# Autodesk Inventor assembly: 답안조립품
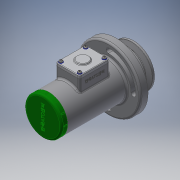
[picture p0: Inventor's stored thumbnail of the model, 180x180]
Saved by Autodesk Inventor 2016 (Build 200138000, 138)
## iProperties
Created: 2017-05
Part Number: 답안조립품
Material: 일반
Document SubType Name: Assembly
Designer: USER
Author: USER
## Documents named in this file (20)
- C:\Users\USER\Desktop\470508V1004\답안조립품.iam
- C:\Users\USER\Desktop\470508V1004\본체.ipt
- C:\Users\USER\Desktop\470508V1004\사이드 커버.ipt
- 사이드 커버.ipt
- C:\Users\USER\Desktop\470508V1004\축.ipt
- C:\Users\USER\Desktop\470508V1004\베어링 15 x 35 x 11.ipt
- C:\Users\USER\Desktop\470508V1004\부시1.ipt
- C:\Users\USER\Desktop\470508V1004\부시2.ipt
- C:\Users\USER\Desktop\470508V1004\멈춤링 35x1.6.ipt
- C:\Users\USER\Desktop\470508V1004\와셔 10x21.ipt
- C:\Users\USER\Desktop\470508V1004\너트 M10.ipt
- C:\Users\USER\Desktop\470508V1004\멈춤링 15 x 1.ipt
- C:\Users\USER\Desktop\470508V1004\오일 실 15 25 7.ipt
- C:\Users\USER\Desktop\470508V1004\탑 커버.ipt
- C:\Users\USER\Desktop\470508V1004\십자볼트 M3 x 10.ipt
- C:\Users\USER\Desktop\470508V1004\와셔 3x6.ipt
- C:\Users\USER\Desktop\470508V1004\V-벨트풀리.ipt
- C:\Users\USER\Desktop\470508V1004\키 4 x 4 x 18.ipt
- C:\Users\USER\Desktop\470508V1004\와셔 4x16.ipt
- C:\Users\USER\Desktop\470508V1004\볼트 M4 x 10.ipt
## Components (2 placed, 2 different names)
1. V-벨트풀리:1
2. ISO 4017 M4 x 10:1 — 각도:2
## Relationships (1: Angle 1)
- 각도:2 [Angle]: ISO 4017 M4 x 10:1
## Named parameters: d20_d19 = 0, d21_d19 = 0, d22_d19 = 0
